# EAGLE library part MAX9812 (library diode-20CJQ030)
Maxim's MAX9812 Tiny, Low-Cost, Single/Dual-Input, Fixed-Gain Microphone Amplifiers with Integrated Bias Description: The MAX9812/MAX9813 are single/dual-input, 20dB fixed-gain microphone amplifiers. They offer tiny packaging and a low-noise, integrated microphone bias, making them ideal for portable audio applications such as notebook computers, cell phones, and PDAs. These amplifiers feature a 500kHz bandwidth, Rail-to-Rail® outputs, an industry-leading 100dB power-supply rejection ratio, and a very low 0.015% THD+N. Power-saving features include very low 230?A supply current and a total shutdown mode that cuts the combined supply and BIAS currents to only 100nA. The MAX9812 is a single amplifier in a 6-pin SC70 package (2mm x 2.1mm) and the MAX9813 is a dualinput amplifier available in an 8-pin SOT23 (3mm x 3mm) package. The MAX9813 has two inputs allowing two microphones to be multiplexed to a single output. The MAX9812/MAX9813 are offered in two grades. The MAX9812L/MAX9813L are optimized for 3.3V supply operation (2.7V to 3.6V). The MAX9812H/MAX9813H are PC2001 compliant and are optimized for 5V operation (4.5V to 5.5V). Both devices are specified over the -40°C to +85°C extended operating temperature range. Features: PC2001 Compliant 100dB at 217Hz Power-Supply Rejection Ratio Very Low 230?A Quiescent Current Low 0.015% THD+N Available in Two Versions: - MAX9812L/MAX9813L?2.7V to 3.6V - MAX9812H/MAX9813H?4.5V to 5.5V Internal Low-Noise Microphone Bias Supply - 2.3V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
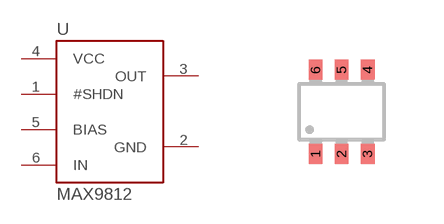
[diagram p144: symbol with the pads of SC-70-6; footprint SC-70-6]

Designator prefix U

## MAX9812  [SC-70-6]
1  #SHDN  in
2  GND  pwr
3  OUT  out
4  VCC  pwr
5  BIAS  in
6  IN  in

## Footprint SC-70-6 (pad centres in mm)
Texas Instruments Package SC-70-6 (-DCK)
smd 0.35 x 0.5: 1 -0.65,-1.05; 2 0,-1.05; 3 0.65,-1.05; 4 0.65,1.05; 5 0,1.05; 6 -0.65,1.05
